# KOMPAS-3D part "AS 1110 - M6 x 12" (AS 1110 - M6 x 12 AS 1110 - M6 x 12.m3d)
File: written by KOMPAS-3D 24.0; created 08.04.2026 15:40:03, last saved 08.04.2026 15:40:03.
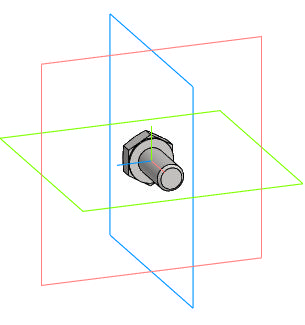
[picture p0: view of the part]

Document properties: Автор: R2D2; Полное имя файла: E:\Работа\Зайцев\VSO1121M-F-S Клапан запорный сальниковый DN.ru\DN15\исходные материалы\AS 1110 - M6 x 12 AS 1110 - M6 x 12.m3d

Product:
- Body: Solid1  | qty 1
- Part/product: AS 1110 - M6 x 12
    Комментарий: Болты и винты   шестигранные точные   метрические ISO
    additional columns: Сталь, мягкая

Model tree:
1. Solid1  (labels: Solid1)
